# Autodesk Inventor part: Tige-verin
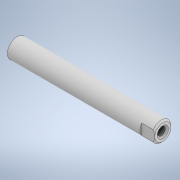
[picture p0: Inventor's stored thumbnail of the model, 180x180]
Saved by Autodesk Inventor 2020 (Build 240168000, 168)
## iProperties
Created: 2023-10
Part Number: Tige-verin
Material: Générique
Document SubType Name: Modeling
Designer: bruno
Density: 1 g/cm^3
Appearance: Par défaut
Author: bruno
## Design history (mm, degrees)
sketch "Esquisse1"
  geometry: C1 r 3 at (0, 0); 1 further point
  constraints: 1 centre point, 1 coincident
  dimensions: "d0" = 6 diameter of C1
extrude "Extrusion1" new body sketch "Esquisse1" distance "d1" = 45; taper "d2" = 0 deg
chamfer "Chanfrein1" distance "d3" = 0.5; stored, may be unused: second distance "d4" = 2, angle "d5" = 45 deg
sketch "Esquisse2"
  geometry: L1 (2.5, 3.588)-(4.483, 3.588); L2 (4.483, 3.588)-(4.483, -5.446); L3 (4.483, -5.446)-(2.5, -5.446); L4 (2.5, -5.446)-(2.5, 3.588); L5 (-6.28, 4.677)-(-2.5, 4.677); L6 (-2.5, 4.677)-(-2.5, -5.446); L7 (-2.5, -5.446)-(-6.28, -5.446); L8 (-6.28, -5.446)-(-6.28, 4.677); 1 further point
  constraints: 16 end point, 4 parallel, 2 horizontal, 2 perpendicular, 1 point on line
  dimensions: "d6" = 2.5 distance from line of L4 point (0, 0); "d7" = 2.5 distance from line of L6 point (0, 0)
extrude "Extrusion2" cut sketch "Esquisse2" distance "d8" = 4; taper "d9" = 0 deg
sketch "Esquisse3"
  geometry: 2 further points
  constraints: 1 coincident
hole "Perçage1" sketch "Esquisse3" at (0, 0) diameter "d10" = 2.459; stored, may be unused: countersink angle "d14" = 90 deg, drill point angle "d16" = 118 deg; dims "d11" = 6, "d12" = 4, "d13" = 2, "d15" = 8.8
chamfer "Chanfrein2" distance "d17" = 0.5; stored, may be unused: second distance "d18" = 2, angle "d19" = 45 deg
node "Solide1"
